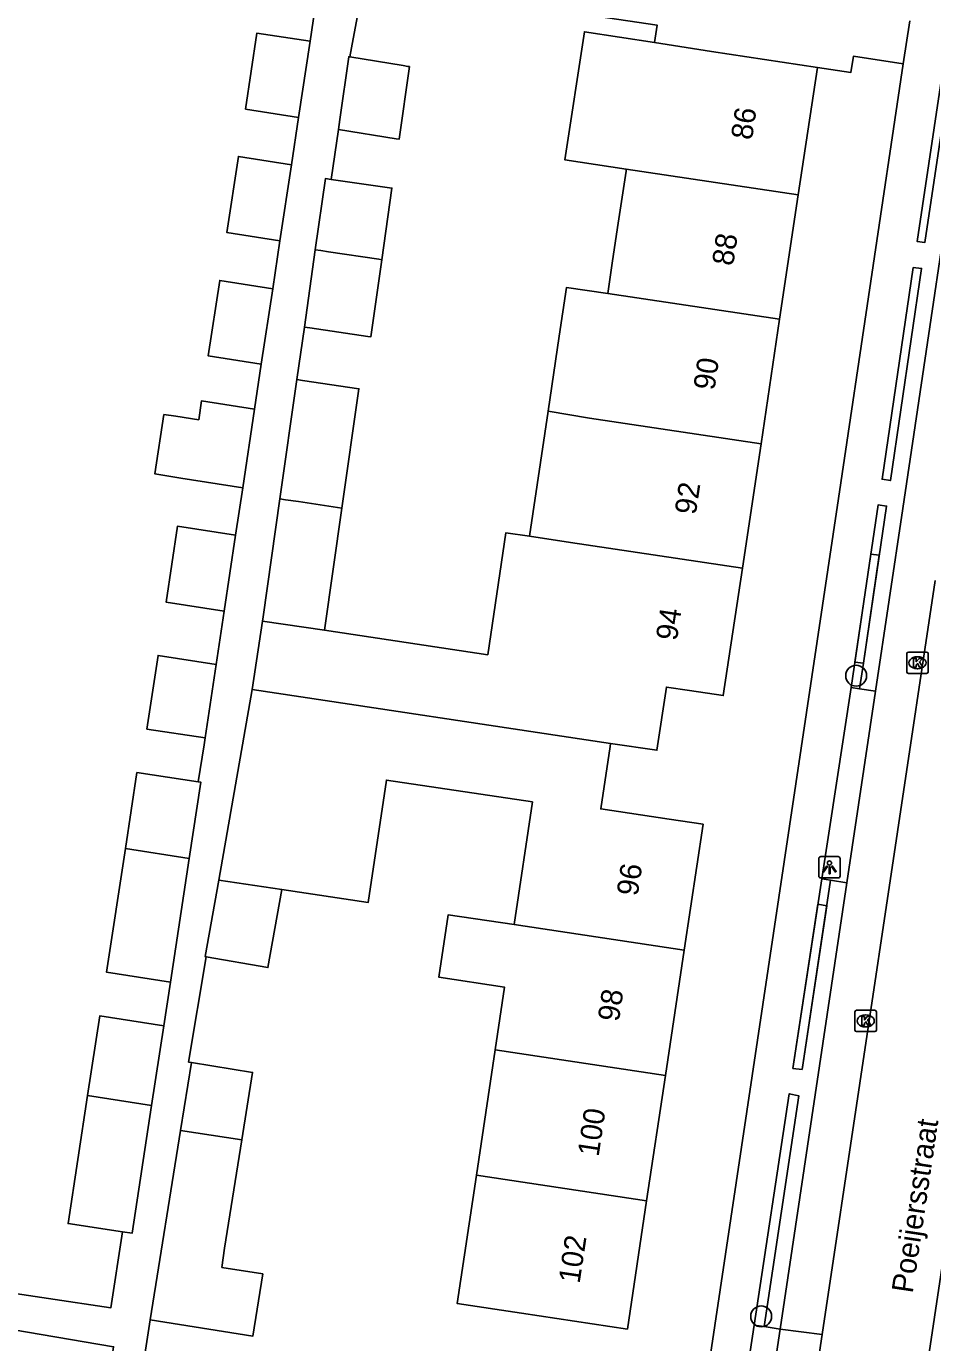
# Model space of a CAD drawing. Extents: x 163010 to 163853, y 382793 to 383982.
# Drawn here: x 163303.7 to 163346, y 383110.7 to 383172.2 of the extents above; entities that cross this region are included whole.
import ezdxf

# ---------------------------------------------------------------- set-up
doc = ezdxf.new("R2010")
doc.units = 0
for name, color, linetype in [('IMGEO_Boom', 7, 'Continuous'), ('IMGEO_Haag', 7, 'Continuous'), ('IMGEO_Kolk', 7, 'Continuous'), ('IMGEO_Lichtpunt', 7, 'Continuous'), ('IMGEO_Openbare_ruimte_label', 7, 'Continuous'), ('IMGEO_Pand', 7, 'Continuous'), ('IMGEO_Pand_nummerreeks', 7, 'Continuous'), ('IMGEO_Parkeervlak_open', 7, 'Continuous'), ('IMGEO_Rijbaan_lokaal_gesloten', 7, 'Continuous'), ('IMGEO_Voetpad_open', 7, 'Continuous')]:
    doc.layers.add(name, color=color, linetype=linetype)

msp = doc.modelspace()

# ---------------------------------------------------------------- linework, layer by layer
at = {"layer": 'IMGEO_Boom'}
for centre in [(163342.463, 383141.856), (163338.027, 383111.934)]:
    msp.add_circle(centre, 0.489, dxfattribs=at)
at = {"layer": 'IMGEO_Haag'}
for points in [[(163342.801, 383142.45), (163342.801, 383142.45), (163343.886, 383149.781), (163343.495, 383149.839), (163342.887, 383145.749)], [(163342.887, 383145.749), (163342.403, 383142.495), (163342.801, 383142.45)], [(163339.948, 383123.467), (163341.091, 383131.106), (163340.678, 383131.182), (163339.502, 383123.514)]]:
    msp.add_lwpolyline(points, dxfattribs=at)
at = {"layer": 'IMGEO_Kolk'}
for p, q in [((163344.828, 383142.036), (163344.828, 383142.888)), ((163344.903, 383142.962), (163345.755, 383142.962)), ((163345.316, 383142.742), (163345.341, 383142.742)), ((163345.829, 383142.888), (163345.829, 383142.036)), ((163345.339, 383142.182), (163345.314, 383142.182)), ((163345.755, 383141.962), (163344.903, 383141.962)), ((163342.409, 383125.308), (163342.409, 383126.16)), ((163342.484, 383126.234), (163343.336, 383126.234)), ((163343.41, 383126.16), (163343.41, 383125.308)), ((163342.897, 383126.014), (163342.922, 383126.014)), ((163343.336, 383125.234), (163342.484, 383125.234)), ((163342.92, 383125.454), (163342.895, 383125.454))]:
    msp.add_line(p, q, dxfattribs=at)
for points in [[(163344.828, 383142.036), (163344.828, 383142.888)], [(163344.903, 383142.962), (163345.755, 383142.962)], [(163345.829, 383142.888), (163345.829, 383142.036)], [(163345.149, 383142.662), (163345.272, 383142.662), (163345.272, 383142.511), (163345.402, 383142.662), (163345.566, 383142.662), (163345.42, 383142.511), (163345.573, 383142.262), (163345.421, 383142.262), (163345.336, 383142.426), (163345.272, 383142.359), (163345.272, 383142.262), (163345.149, 383142.262), (163345.149, 383142.662)], [(163345.755, 383141.962), (163344.903, 383141.962)], [(163342.409, 383125.308), (163342.409, 383126.16)], [(163342.484, 383126.234), (163343.336, 383126.234)], [(163343.41, 383126.16), (163343.41, 383125.308)], [(163342.73, 383125.934), (163342.853, 383125.934), (163342.853, 383125.783), (163342.983, 383125.934), (163343.147, 383125.934), (163343.001, 383125.783), (163343.154, 383125.534), (163343.002, 383125.534), (163342.917, 383125.698), (163342.853, 383125.631), (163342.853, 383125.534), (163342.73, 383125.534), (163342.73, 383125.934)], [(163343.336, 383125.234), (163342.484, 383125.234)]]:
    msp.add_lwpolyline(points, dxfattribs=at)
for centre, start, end in [((163344.905, 383142.886), 91.55205, 178.44795), ((163344.905, 383142.886), 91.55205, 178.44795), ((163345.753, 383142.886), 1.55205, 88.44795), ((163345.753, 383142.886), 1.55205, 88.44795), ((163344.905, 383142.038), 181.55205, 268.44795), ((163344.905, 383142.038), 181.55205, 268.44795), ((163345.753, 383142.038), 271.55205, 358.44795), ((163345.753, 383142.038), 271.55205, 358.44795), ((163342.486, 383126.158), 91.55205, 178.44795), ((163342.486, 383126.158), 91.55205, 178.44795), ((163343.334, 383126.158), 1.55205, 88.44795), ((163343.334, 383126.158), 1.55205, 88.44795), ((163342.486, 383125.31), 181.55205, 268.44795), ((163342.486, 383125.31), 181.55205, 268.44795), ((163343.334, 383125.31), 271.55205, 358.44795), ((163343.334, 383125.31), 271.55205, 358.44795)]:
    msp.add_arc(centre, 0.0765, start, end, dxfattribs=at)
for centre, major_axis, ratio, start_param, end_param in [((163345.315, 383142.462), (-0.387, 0.002), 0.722429, 4.712389, 7.853982), ((163345.34, 383142.462), (-0.39, 0.002), 0.717154, 1.570796, 4.712389), ((163342.896, 383125.734), (-0.387, 0.002), 0.722429, 4.712389, 7.853982), ((163342.921, 383125.734), (-0.39, 0.002), 0.717154, 1.570796, 4.712389)]:
    msp.add_ellipse(centre, major_axis=major_axis, ratio=ratio, start_param=start_param, end_param=end_param, dxfattribs=at)
at = {"layer": 'IMGEO_Lichtpunt'}
for p, q in [((163340.719, 383133.312), (163340.719, 383132.505)), ((163340.719, 383133.312), (163340.719, 383132.505)), ((163341.621, 383133.407), (163340.813, 383133.407)), ((163341.621, 383133.407), (163340.813, 383133.407)), ((163341.715, 383132.505), (163341.715, 383133.312)), ((163341.715, 383132.505), (163341.715, 383133.312)), ((163340.813, 383132.411), (163341.621, 383132.411)), ((163340.813, 383132.411), (163341.621, 383132.411))]:
    msp.add_line(p, q, dxfattribs=at)
for points in [[(163341.093, 383132.976), (163341.132, 383132.948), (163340.944, 383132.686), (163340.906, 383132.713), (163341.093, 383132.976)], [(163341.195, 383132.928), (163341.242, 383132.928), (163341.242, 383132.606), (163341.195, 383132.606), (163341.195, 383132.928)], [(163341.305, 383132.948), (163341.343, 383132.975), (163341.53, 383132.713), (163341.491, 383132.685), (163341.305, 383132.948)]]:
    msp.add_lwpolyline(points, dxfattribs=at)
msp.add_circle((163341.218, 383133.11), 0.0994, dxfattribs=at)
for centre, start, end in [((163340.813, 383133.312), 90, 180), ((163340.813, 383133.312), 90, 180), ((163341.621, 383133.312), 0, 90), ((163341.621, 383133.312), 0, 90), ((163340.813, 383132.505), 180, 270), ((163340.813, 383132.505), 180, 270), ((163341.621, 383132.505), 270, 0), ((163341.621, 383132.505), 270, 360)]:
    msp.add_arc(centre, 0.0946, start, end, dxfattribs=at)
at = {"layer": 'IMGEO_Pand'}
for points in [[(163316.948, 383171.499), (163314.469, 383171.872), (163313.935, 383168.323), (163316.411, 383167.934)], [(163331.726, 383165.514), (163328.856, 383165.944), (163329.765, 383171.932), (163333.049, 383171.423)], [(163316.948, 383171.499), (163316.411, 383167.934)], [(163333.049, 383171.423), (163335.71, 383171.011), (163340.654, 383170.27)], [(163318.272, 383167.37), (163318.338, 383167.834), (163318.755, 383170.764), (163318.811, 383170.755)], [(163318.272, 383167.37), (163320.978, 383166.932), (163321.113, 383166.911), (163321.595, 383170.305), (163321.525, 383170.316), (163321.305, 383170.352), (163318.811, 383170.755)], [(163340.654, 383170.27), (163339.761, 383164.312)], [(163316.078, 383165.723), (163313.602, 383166.112), (163313.066, 383162.556), (163315.542, 383162.168)], [(163316.078, 383165.723), (163315.542, 383162.168)], [(163331.726, 383165.514), (163331.713, 383165.425), (163331.35, 383163), (163331.085, 383161.233), (163330.856, 383159.704)], [(163339.761, 383164.312), (163331.726, 383165.514)], [(163317.196, 383161.749), (163317.669, 383165.075), (163317.932, 383165.038)], [(163320.3, 383161.284), (163320.777, 383164.633), (163317.932, 383165.038)], [(163338.89, 383158.502), (163339.761, 383164.312)], [(163316.684, 383158.143), (163317.196, 383161.749)], [(163317.196, 383161.749), (163317.46, 383161.709), (163317.808, 383161.657), (163320.162, 383161.304), (163320.3, 383161.284)], [(163320.3, 383161.284), (163319.788, 383157.679), (163319.65, 383157.7), (163316.947, 383158.104), (163316.684, 383158.143)], [(163315.205, 383159.932), (163312.729, 383160.32), (163312.197, 383156.789), (163314.673, 383156.4)], [(163315.205, 383159.932), (163314.673, 383156.4)], [(163330.856, 383159.704), (163328.938, 383159.991), (163328.596, 383157.709), (163328.073, 383154.217)], [(163330.856, 383159.704), (163338.89, 383158.502)], [(163338.019, 383152.692), (163338.89, 383158.502)], [(163315.542, 383150.115), (163316.335, 383155.689)], [(163316.335, 383155.689), (163316.599, 383155.65), (163319.231, 383155.256), (163318.438, 383149.683)], [(163314.358, 383154.309), (163311.882, 383154.698), (163311.748, 383153.81), (163310.677, 383153.971), (163310.12, 383154.055), (163309.702, 383151.279), (163310.259, 383151.192), (163310.916, 383151.089), (163313.805, 383150.636)], [(163314.358, 383154.309), (163313.805, 383150.636)], [(163327.197, 383148.369), (163328.073, 383154.217)], [(163328.073, 383154.217), (163330.006, 383153.891), (163338.019, 383152.692)], [(163338.019, 383152.692), (163337.149, 383146.882)], [(163314.731, 383144.41), (163314.758, 383144.6), (163315.542, 383150.115)], [(163315.542, 383150.115), (163315.806, 383150.076), (163316.406, 383149.986), (163318.438, 383149.683)], [(163318.438, 383149.683), (163317.626, 383143.976)], [(163312.936, 383144.869), (163310.222, 383145.295), (163310.756, 383148.838), (163313.47, 383148.413)], [(163313.47, 383148.413), (163312.936, 383144.869)], [(163317.626, 383143.976), (163325.249, 383142.834), (163326.103, 383148.531), (163327.197, 383148.369)], [(163337.149, 383146.882), (163329.119, 383148.083), (163327.197, 383148.369)], [(163330.989, 383138.697), (163333.154, 383138.372), (163333.596, 383141.324), (163334.674, 383141.163), (163336.256, 383140.926), (163337.149, 383146.882)], [(163314.252, 383141.206), (163314.731, 383144.41)], [(163317.626, 383143.976), (163314.731, 383144.41)], [(163312.561, 383142.381), (163309.847, 383142.806), (163309.328, 383139.364), (163312.044, 383138.954)], [(163312.561, 383142.381), (163312.044, 383138.954)], [(163312.685, 383132.309), (163314.252, 383141.206)], [(163330.989, 383138.697), (163314.252, 383141.206)], [(163334.427, 383129.034), (163335.31, 383134.923), (163333.728, 383135.16), (163330.531, 383135.638), (163330.966, 383138.545), (163330.989, 383138.697)], [(163308.322, 383133.786), (163308.864, 383137.335), (163311.73, 383136.896)], [(163311.73, 383136.896), (163311.85, 383136.878), (163311.306, 383133.318)], [(163315.627, 383131.866), (163319.658, 383131.259), (163320.516, 383136.985), (163327.337, 383135.962), (163326.479, 383130.234)], [(163310.425, 383127.55), (163307.44, 383128.018), (163308.322, 383133.786)], [(163308.322, 383133.786), (163311.306, 383133.318)], [(163311.306, 383133.318), (163310.425, 383127.55)], [(163312.091, 383128.733), (163312.056, 383128.739), (163312.685, 383132.309)], [(163315.627, 383131.866), (163312.685, 383132.309)], [(163312.091, 383128.733), (163314.985, 383128.223), (163315.627, 383131.866)], [(163325.602, 383124.382), (163326.04, 383127.309), (163322.967, 383127.77), (163323.405, 383130.694), (163326.479, 383130.234)], [(163326.479, 383130.234), (163334.427, 383129.034)], [(163334.427, 383129.034), (163333.551, 383123.185)], [(163310.113, 383125.511), (163307.129, 383125.979), (163306.56, 383122.254)], [(163310.113, 383125.511), (163309.544, 383121.785)], [(163324.725, 383118.534), (163325.602, 383124.382)], [(163325.602, 383124.382), (163333.551, 383123.185)], [(163310.902, 383120.616), (163311.411, 383123.789)], [(163313.762, 383120.185), (163314.266, 383123.331), (163311.411, 383123.789)], [(163333.551, 383123.185), (163332.674, 383117.337)], [(163308.19, 383115.881), (163305.646, 383116.27), (163306.56, 383122.254)], [(163306.56, 383122.254), (163309.544, 383121.785)], [(163309.544, 383121.785), (163308.632, 383115.813), (163308.19, 383115.881)], [(163309.485, 383111.773), (163310.902, 383120.616)], [(163310.902, 383120.616), (163313.762, 383120.185)], [(163309.485, 383111.773), (163314.273, 383111.005), (163314.739, 383113.914), (163312.829, 383114.22), (163312.948, 383115.114), (163313.762, 383120.185)], [(163332.674, 383117.337), (163331.776, 383111.342), (163326.832, 383112.083), (163323.826, 383112.534), (163324.725, 383118.534)], [(163332.674, 383117.337), (163324.725, 383118.534)]]:
    msp.add_lwpolyline(points, dxfattribs=at)
at = {"layer": 'IMGEO_Parkeervlak_open'}
for points in [[(163347.005, 383171.031), (163345.665, 383162.083), (163345.314, 383162.138), (163346.651, 383171.089)], [(163325.006, 383038.94), (163341.637, 383150.129), (163344.666, 383170.44)], [(163343.37, 383141.133), (163344.647, 383149.662), (163347.799, 383170.932)], [(163345.135, 383160.921), (163345.522, 383160.883), (163344.061, 383150.968), (163343.672, 383151.034), (163345.135, 383160.921)], [(163342.887, 383145.749), (163343.153, 383147.538), (163343.545, 383147.48), (163342.801, 383142.45)], [(163342.226, 383141.307), (163342.887, 383145.749)], [(163342.801, 383142.45), (163342.623, 383141.247)], [(163339.502, 383123.514), (163340.86, 383132.369)], [(163341.271, 383132.306), (163339.948, 383123.467)], [(163338.907, 383111.332), (163342.03, 383132.19)], [(163339.948, 383123.467), (163339.502, 383123.514)], [(163337.704, 383111.517), (163339.334, 383122.331), (163339.778, 383122.237), (163338.168, 383111.467)]]:
    msp.add_lwpolyline(points, dxfattribs=at)
at = {"layer": 'IMGEO_Rijbaan_lokaal_gesloten'}
for points in [[(163340.877, 383111.094), (163346.155, 383146.302)], [(163351.16, 383145.514), (163333.064, 383024.594)], [(163339.666, 383103.012), (163340.877, 383111.094)]]:
    msp.add_lwpolyline(points, dxfattribs=at)
at = {"layer": 'IMGEO_Voetpad_open'}
for points in [[(163294.265, 383178.498), (163313.908, 383175.415), (163317.457, 383174.88), (163316.948, 383171.499)], [(163318.811, 383170.755), (163318.88, 383171.184), (163319.469, 383174.281), (163333.171, 383172.238), (163333.049, 383171.423)], [(163344.666, 383170.44), (163344.964, 383172.44)], [(163340.654, 383170.27), (163342.22, 383170.035), (163342.333, 383170.788), (163344.666, 383170.44)], [(163316.411, 383167.934), (163316.078, 383165.723)], [(163317.932, 383165.038), (163318.272, 383167.37)], [(163315.542, 383162.168), (163315.205, 383159.932)], [(163316.335, 383155.689), (163316.684, 383158.143)], [(163314.673, 383156.4), (163314.358, 383154.309)], [(163313.805, 383150.636), (163313.47, 383148.413)], [(163312.936, 383144.869), (163312.561, 383142.381)], [(163340.86, 383132.369), (163342.226, 383141.307)], [(163343.37, 383141.133), (163342.03, 383132.19)], [(163342.226, 383141.307), (163342.623, 383141.247)], [(163342.623, 383141.247), (163343.37, 383141.133)], [(163312.044, 383138.954), (163311.996, 383138.634), (163311.73, 383136.896)], [(163341.271, 383132.306), (163340.86, 383132.369)], [(163342.03, 383132.19), (163341.271, 383132.306)], [(163311.411, 383123.789), (163311.274, 383123.811), (163312.091, 383128.733)], [(163310.425, 383127.55), (163310.113, 383125.511)], [(163308.19, 383115.881), (163307.648, 383112.336), (163293.062, 383114.515)], [(163296.334, 383112.464), (163307.77, 383110.513), (163307.575, 383109.184)], [(163305.994, 383089.254), (163306.126, 383090.074), (163309.485, 383111.773)], [(163336.468, 383103.432), (163337.704, 383111.517)], [(163338.907, 383111.332), (163337.702, 383103.259)], [(163338.168, 383111.467), (163337.704, 383111.517)], [(163338.168, 383111.467), (163338.907, 383111.332)], [(163338.907, 383111.332), (163340.877, 383111.094)]]:
    msp.add_lwpolyline(points, dxfattribs=at)

# ---------------------------------------------------------------- texts
at = {"layer": 'IMGEO_Openbare_ruimte_label'}
msp.add_text('Poeijersstraat', height=1, rotation=81.54574, dxfattribs=at).set_placement((163345.103, 383112.985))
at = {"layer": 'IMGEO_Pand_nummerreeks'}
for s, rotation, p in [('86', 81.4746, (163337.594, 383166.847)), ('88', 81.4746, (163336.712, 383160.966)), ('90', 81.4746, (163335.841, 383155.156)), ('92', 81.4746, (163334.969, 383149.34)), ('94', 81.4746, (163334.088, 383143.46)), ('96', 81.4746, (163332.255, 383131.534)), ('98', 81.47672, (163331.375, 383125.668)), ('100', 81.47672, (163330.43, 383119.366)), ('102', 81.47672, (163329.541, 383113.438))]:
    msp.add_text(s, height=1, rotation=rotation, dxfattribs=at).set_placement(p)

doc.saveas('drawing.dxf')
